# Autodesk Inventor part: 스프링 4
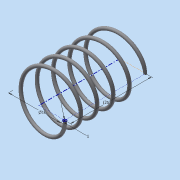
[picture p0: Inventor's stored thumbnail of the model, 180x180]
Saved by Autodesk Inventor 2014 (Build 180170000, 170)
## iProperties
Created: 2015-06
Part Number: 스프링 4
Material: 강철, 연강
Document SubType Name: Modeling
Designer: Administrator
Density: 7.86 g/cm^3
Appearance: 강철
Mass: 1.53535 g
Surface Area: 7.89042 cm^2
Volume: 0.195337 cm^3
Author: Administrator
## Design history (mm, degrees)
sketch "스케치1"
  geometry: L1 (0, 0)-(8, 0); L2 (8, 0)-(8, 21.5); L3 (8, 21.5)-(0, 21.5); L4 (0, 21.5)-(0, 0); C1 r 0.5 at (8, 0)
  constraints: 8 end point, 2 parallel, 1 centre point, 1 coincident, 1 horizontal, 1 perpendicular
  dimensions: "d0" = 1 diameter of C1; "d1" = 16 diameter of L2 L4; "d2" = 21.5 distance of L1.end L2.end (derived)
feature "코일1" pitch "d3" = 10; turns "d5" = 5; dims "d4" = 21.5 (= d2), "d6" = 0, angle "d7" = 90 deg, angle "d8" = 90 deg, "d9" = 0, "d10" = 0
sketch "스케치2"
  geometry: L1 (-8.5, 0)-(-7.5, 0) reference; L2 (-8.5, 0)-(-7.5, 0) reference; 1 further point
  constraints: 2 horizontal alignment
extrude "돌출1" cut sketch "스케치2" stored distance "d11" = 10; taper "d12" = 0 deg
node "작업 평면1"
sketch "스케치3"
  geometry: L1 (8.5, 0)-(7.5, 0) reference; 1 further point
  constraints: 1 horizontal alignment
extrude "돌출2" cut sketch "스케치3" stored distance "d14" = 10; taper "d15" = 0 deg
node "솔리드1"
node "절단 모서리 투영1"
node "절단 모서리 투영2"
node "절단 모서리 투영3"
other parameters: "d13" = -21.5 (= -d2)
